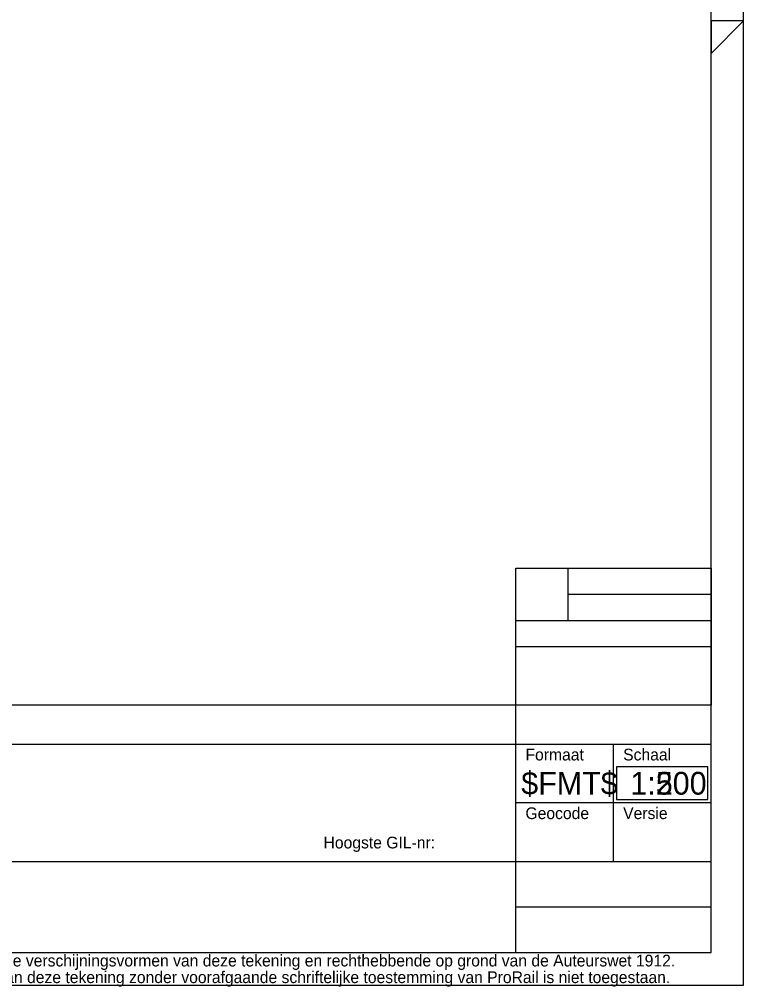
# Model space of a CAD drawing. Extents: x 0 to 1051, y 0 to 297.
# Drawn here: x 939.8 to 1051, y -0.2 to 148.2 of the extents above; entities that cross this region are included whole.
import ezdxf

# ---------------------------------------------------------------- set-up
doc = ezdxf.new("R2010")
doc.units = 0
for name, color, linetype in [('KADER-LIJNEN-018', 7, 'Continuous'), ('KADER-LIJNEN-050', 7, 'Continuous'), ('TITEL-DETAIL', 7, 'Continuous'), ('TITEL-DETAIL (1-200)', 7, 'Continuous'), ('TITEL-DETAIL (1-500)', 7, 'Continuous'), ('TITEL-HOOGSTE-GIL', 7, 'Continuous'), ('TITEL-LIJNEN-050', 7, 'Continuous'), ('TITEL-TEKSTEN-018', 7, 'Continuous'), ('TITEL-TEKSTEN-035', 7, 'Continuous')]:
    doc.layers.add(name, color=color, linetype=linetype)

msp = doc.modelspace()

# ---------------------------------------------------------------- linework, layer by layer
at = {"layer": 'KADER-LIJNEN-018'}
for p, q in [((1051, 0), (1051, 297)), ((1051, 148), (1046, 148)), ((1046, 148), (1046, 143)), ((1046, 143), (1051, 148)), ((0, 0), (1051, 0))]:
    msp.add_line(p, q, dxfattribs=at)
at = {"layer": 'KADER-LIJNEN-050'}
msp.add_lwpolyline([(25, 5), (1046, 5), (1046, 292), (25, 292)], close=True, dxfattribs=at)
at = {"layer": 'TITEL-DETAIL'}
msp.add_lwpolyline([(1031.5, 28.5), (1045.5, 28.5), (1045.5, 33.5), (1031.5, 33.5)], close=True, dxfattribs=at)
at = {"layer": 'TITEL-LIJNEN-050'}
for p, q in [((1024, 64), (1024, 56)), ((1024, 60), (1046, 60)), ((1016, 56), (1046, 56)), ((1016, 52), (1046, 52)), ((1016, 5), (1016, 43)), ((866, 37), (1046, 37)), ((1031, 19), (1031, 37)), ((1046, 28), (1016, 28)), ((866, 19), (1046, 19)), ((1046, 12), (1016, 12))]:
    msp.add_line(p, q, dxfattribs=at)
msp.add_lwpolyline([(1016, 43), (1016, 64), (1046, 64), (1046, 43)], dxfattribs=at)
msp.add_lwpolyline([(866, 5), (1046, 5), (1046, 43), (866, 43)], close=True, dxfattribs=at)

# ---------------------------------------------------------------- texts
at = {"layer": 'TITEL-DETAIL (1-200)'}
msp.add_text('1:200', height=3.5, dxfattribs=at).set_placement((1033.6, 29.25))
at = {"layer": 'TITEL-DETAIL (1-500)'}
msp.add_text('1:500', height=3.5, dxfattribs=at).set_placement((1033.6, 29.25))
at = {"layer": 'TITEL-HOOGSTE-GIL'}
msp.add_text('Hoogste GIL-nr:', height=1.8, dxfattribs=at).set_placement((986.5, 21))
at = {"layer": 'TITEL-TEKSTEN-018'}
for s, p in [('Formaat', (1017.5, 34.5)), ('Schaal', (1032.5, 34.5)), ('Geocode', (1017.5, 25.5)), ('Versie', (1032.5, 25.5)), ('ProRail is eigenaar van alle digitale en analoge verschijningsvormen van deze tekening en rechthebbende op grond van de Auteurswet 1912.', (889.95, 2.88)), ('Wijziging, vermenigvuldiging en/of openbaarmaking van deze tekening zonder voorafgaande schriftelijke toestemming van ProRail is niet toegestaan.', (880.77, 0.33))]:
    msp.add_text(s, height=1.8, dxfattribs=at).set_placement(p)
at = {"layer": 'TITEL-TEKSTEN-035'}
msp.add_text('$FMT$', height=3.5, dxfattribs=at).set_placement((1016.85, 29.25))

doc.saveas('drawing.dxf')
